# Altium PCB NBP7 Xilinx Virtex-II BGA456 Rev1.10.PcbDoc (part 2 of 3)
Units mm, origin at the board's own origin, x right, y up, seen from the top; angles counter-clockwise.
Board outline 69 x 80.99 mm, 6 copper layers (Top Layer, MidLayer1, InternalPlane1, InternalPlane2, MidLayer2, Bottom Layer); 101 components, 273 nets, 963 pads, 545 vias.
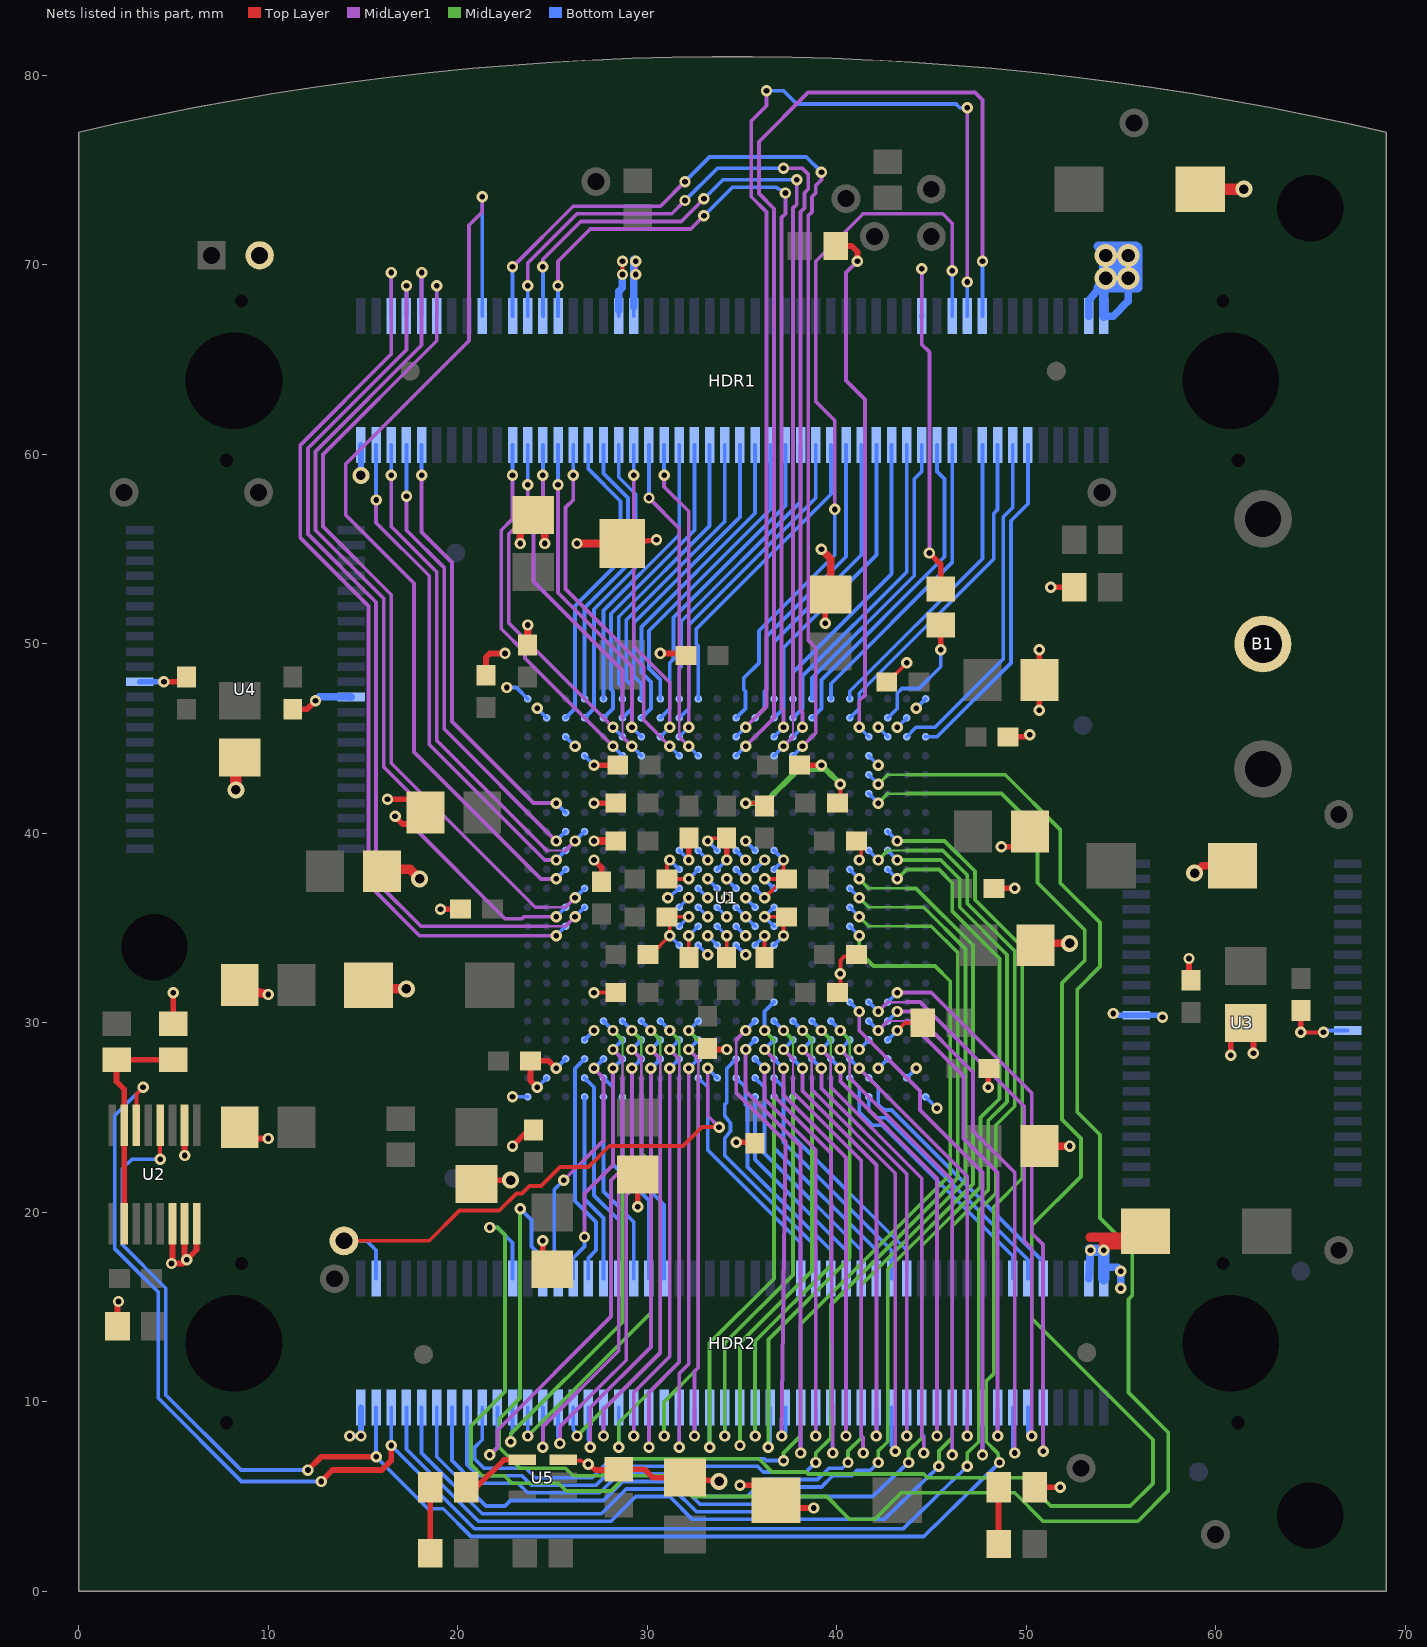
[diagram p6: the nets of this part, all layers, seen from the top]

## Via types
v1: diameter 0.6, hole 0.3, Top Layer to Bottom Layer, tented bottom, 520 vias
v2: diameter 0.9, hole 0.5, Top Layer to Bottom Layer, 17 vias
v3: diameter 1.2, hole 0.7, Top Layer to Bottom Layer, 8 vias

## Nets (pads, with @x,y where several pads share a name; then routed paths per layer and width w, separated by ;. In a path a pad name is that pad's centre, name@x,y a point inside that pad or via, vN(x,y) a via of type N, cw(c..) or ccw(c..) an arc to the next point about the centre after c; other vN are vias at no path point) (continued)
GND: B1.2 C1.2 C2.2 C3.2 C4.2 C5.2 C6.2 C7.2 C8.2 C9.2 C10.2 C11.2 C12.2 C13.2 C14.2 C15.2 C16.2 C17.2 C18.2 C19.2 C20.2 C22.2 C23.2 C24.2 C25.2 C26.2 C27.2 C28.2 C29.2 C30.2 C31.2 C32.2 C33.2 C34.2 C35.2 C36.2 C37.2 C38.2 C39.2 C40.2 C41.2 C42.2 C43.2 C44.2 C45.2 C46.2 C47.2 C48.2 C49.2 C50.2 C51.2 C52.2 C53.2 C54.2 C55.2 C56.2 C57.2 C58.2 C59.2 C60.2 C61.2 C62.2 HDR1.1 HDR1.36 HDR1.38 HDR1.98 HDR1.100 HDR2.1 HDR2.98 HDR2.100 JP1.2 LED1.2 R9.2 R10.1 U1.A1 U1.A22 U1.AA2 U1.AA21 U1.AB1 U1.AB22 U1.B2 U1.B21 U1.C3 U1.C20 U1.D4 U1.D19 U1.J9 U1.J10 U1.J11 U1.J12 U1.J13 U1.J14 U1.K9 U1.K10 U1.K11 U1.K12 U1.K13 U1.K14 U1.L9 U1.L10 U1.L11 U1.L12 U1.L13 U1.L14 U1.M9 U1.M10 U1.M11 U1.M12 U1.M13 U1.M14 U1.N9 U1.N10 U1.N11 U1.N12 U1.N13 U1.N14 U1.P9 U1.P10 U1.P11 U1.P12 U1.P13 U1.P14 U1.W4 U1.W19 U1.Y3 U1.Y20 U2.6 U2.7 U2.8 U2.10 U3.12 U3.34 U4.12 U4.34 U5.3 | length 241
  Top Layer w0.2: C7.2@8.5,44.3 8.638,44.092 8.9,43.7 C7.2@9,43.2 ; C3.2@20.5,22 20.639,21.414 C3.2@20.644,21.398 ; U5.3@25.6,7 25.9,6.9 26.5,6.9 v1(26.9,6.7) ; v1(27.2,31.6) C50.2@28.2,31.6 ; C45.2@28.2,39.6 C45.2@28.35,39.6 ; v1(28.7,69.5) v1(28.7,70.2) ; v1(29.5,20.3) C4.2@29.5,22 ; C43.2@30.05,33.6 30.2,33.6 v1(31.2,34.6) C32.2@31.2,35.6 ; C32.2@31.05,35.6 C32.2@31.2,35.6 ; v1(31.2,38.6) 31.05,38.45 C37.2@31.05,37.6 v1(32.2,37.6) ; C36.2@32.2,33.45 v1(32.2,34.6) ; v1(32.2,35.6) C32.2@31.2,35.6 ; v1(33.2,39.6) 33.3,39.6 33.45,39.75 C25.2@34.2,39.75 ; C26.2@34.2,33.45 v1(34.2,34.6) ; v1(35.2,41.6) C19.2@36.1,41.6 ; C20.2@36.2,33.45 v1(36.2,34.6) ; v1(36.2,35.6) C31.2@37.3,35.6 ; v1(36.2,36.6) 37,37.4 C30.2@37.1,37.4 ; v1(36.2,37.6) C30.2@37.35,37.6 37.35,37.75 37.2,37.9 v1(37.2,38.6) ; C56.2@36.8,4.4 v1(38.8,4.4) ; v1(37.2,34.6) C31.2@37.2,35.4 ; C48.2@40.05,31.6 40.2,31.6 v1(40.2,32.6) 40.2,33.3 40.4,33.5 40.7,33.5 40.994,33.412 C47.2@41.2,33.35 ; C44.2@40.2,41.6 v1(40.2,42.6) ; C46.2@40.95,39.35 C46.2@40.95,39.6 ; v1(41.2,38.6) 41.3,38.7 C46.2@41.3,39.4 ; C22.2@42.65,48 C22.2@42.7,48 ; C22.2@42.8,48 C22.2@42.7,48 ; v1(43.7,49) C22.2@42.7,48 ; C39.2@47.95,27.6 C39.2@48.05,27.6 C39.2@48.047,27.548 ; C34.2@48.6,45.1 C34.2@49.05,45.1 ; v1(49.4,37.1) v1@49.45,37.1 ; C16.2@49.5,40 C16.2@49.7,40.1 ; C13.2@50.4,47.7 50.7,47.76 C13.2@50.765,47.773 ; LED1.2@50.45,5.5 LED1.2@50.6,5.5 ; C15.2@50.825,23.975 51.325,24.35 50.7,24.2 50.94,23.72 50.98,23.64 51,23.6 51.1,23.4 51.1,23.5 51.1,23.7 C15.2@51.2,23.5 ; C33.2@58.5,32.35 C33.2@58.6,32.35 ; C33.2@58.6,32.3 C33.2@58.6,32.349 ; v1(58.6,33.4) C33.2@58.6,32.35 ; C33.2@58.7,32.25 C33.2@58.6,32.349 ; v1(60.8,28.3) C2.2@60.8,29.6 ; v1(62,28.4) C2.2@62,29.5 ; v1(64.5,29.5) v1(65.7,29.5) ; C33.2@58.6,32.349 58.5,32.35 C33.2@58.6,32.35
  Top Layer w0.3: R10.1@2.05,14 2.05,15.25 v1(2.1,15.3) ; v1(4.5,48) C41.2@5.7,48 ; C51.2@4.8,30.1 4.865,29.905 C51.2@5,29.5 ; U2.6@4.952,19.4 4.952,17.353 v1(4.9,17.3) 5.5,17.3 v1(5.7,17.5) ; C51.2@5,29.95 v1(5,31.6) ; U2.10@5.587,24.6 5.587,23.012 v1(5.6,23) ; U2.7@5.6,19.387 U2.7@5.587,19.4 5.587,17.612 v1(5.7,17.5) ; U2.8@6.222,19.4 6.222,18.023 v1(5.7,17.5) ; C9.2@8.5,23.9 v1(10,23.9) ; C42.2@11.3,46.55 12.05,46.55 v1(12.5,47) ; v1(16.3,41.8) 17.6,41.8 C11.2@17.9,41.7 ; v1(16.7,40.9) 17.1,40.5 C11.2@17.9,40.5 ; v1(19.1,36) C28.2@20.15,36 ; C3.2@21,21.7 v2(22.8,21.7) ; C24.2@21.5,48.3 C24.2@21.5,48.35 21.5,49.3 21.7,49.5 v1(22.5,49.5) ; v1(22.9,23.5) 23.75,24.35 C27.2@24,24.35 ; v1(24.2,26.6) 23.85,26.95 C38.2@23.85,28 24.8,28 v1(25.2,27.6) ; v1(24.5,18.5) 24.5,17.5 C14.2@24.9,17.5 ; v1(26.9,6.7) 27.3,6.4 C52.2@28.5,6.4 ; v1(27.2,38.6) 27.6,38.2 C59.2@27.6,37.45 ; v1(27.2,41.6) C49.2@28.3,41.6 ; v1(27.2,43.6) C61.2@28.45,43.6 ; C52.2@28.5,6.45 29.85,6.45 30.3,6 C1.2@32,6 v2(33.8,5.8) ; C53.2@28.7,55.3 v1(30.5,55.5) ; v1(29.5,20.3) C4.2@29.5,21.9 ; v1@30.7,49.6 v1(30.7,49.5) 31.8,49.5 C35.2@32.05,49.4 ; v1(32.2,38.6) C40.2@32.2,39.75 ; C62.2@33.2,28.65 33.25,28.6 v1(34.2,28.6) ; v1(34.2,38.6) C25.2@34.2,39.75 ; v1(34.7,23.7) C17.2@35.7,23.7 ; v1(34.9,5.6) C56.2@36.6,5.6 ; C56.2@36.5,4.4 36.8,4.4 v1(38.8,4.4) ; C60.2@38.05,43.6 38.35,43.75 38.3,43.6 v1(39.2,43.6) ; v1(39.4,51.1) 39.4,52.6 39.697,52.631 C5.2@39.7,52.631 ; C5.2@39.5,53 39.7,52.9 C5.2@39.7,52.644 ; C5.2@39.6,52.7 C5.2@39.7,52.644 ; C5.2@39.7,52.6 C5.2@39.7,52.631 ; v1(48,26.6) C39.2@48,27.55 ; C29.2@48.3,37.1 v1(49.4,37.1) ; v1(48.7,39.3) 49.4,39.3 C16.2@50.2,40.1 ; C34.2@49.05,45.1 49.9,45.1 ; LED1.2@50.6,5.5 v1(51.8,5.5) ; v1(50.7,46.5) 50.7,47.76 C13.2@50.7,48.1 v1(50.7,49.7) ; v1(51.3,53) R9.2@52.55,53 ; R9.2@52.55,52.9 R9.2@52.6,52.9 ; C33.2@58.6,32.35 v1(58.6,33.4) ; v1(60.8,28.3) C2.2@60.8,29.8 ; v1(62,28.4) C2.2@62,29.6 ; v1(64.5,29.5) C18.2@64.5,30.65 ; C5.2@39.7,52.631 39.719,52.633 C5.2@39.7,52.644 ; C5.2@39.7,52.631 C5.2@39.7,52.644
  Top Layer w0.4: C8.2@7.85,31.35 C8.2@7.9,31.4 ; v1(23.3,55.3) 23.3,56.3 C12.2@24,56.8 ; C23.2@23.7,50.1 v1(23.7,51) ; v1(24.6,55.3) C12.2@24.6,56.5 ; v1(26.3,55.3) C53.2@28.7,55.3 ; v1(27.2,39.6) C45.2@28.35,39.6 ; v1(39.2,55) 39.7,54.5 39.7,52.9 39.7,52.644 39.7,52.631 C5.2@39.7,52.6 ; C6.2@50.7,34.2 v2(52.3,34.2) ; C15.2@51.2,23.5 v1(52.3,23.5) ; v2(58.9,37.9) 59.3,38.3 C55.2@60.9,38.3
  Top Layer w0.5: C8.2@8.5,31.8 v1(10,31.5) ; C54.2@15.3,31.5 15.5,31.8 v2(17.3,31.8) ; C10.2@16,38.1 C10.2@16.9,38.1 ; C10.2@16.903,38.06 C10.2@16.9,38.1 ; v2(18,37.6) 17.5,38.1 C10.2@16.9,38.1 ; C6.2@50.5,34.2 C6.2@50.7,34.2 ; 53.4,18.7 54.1,18.7 ; v1(54.1,18) 54.1,18.3 ; C57.2@55.3,18.3 54.1,18.3 ; C57.2@56,18.7 54.1,18.7 ; 54.1,18.3 54.1,18.7
  Top Layer w0.6: v2(8.3,42.3) C7.2@8.3,44 ; C58.2@59.2,74 v2(61.5,74)
  MidLayer1 w0.2: v1(29.4,69.5) v1(29.4,70.2)
  MidLayer2 w0.3: v1(35.2,41.6) 36.2,41.6 38,43.4 39.2,43.4 39.4,43.4 v1(40.2,42.6)
  Bottom Layer w0.2: v1(22.6,47.7) 23.1,47.7 U1.AB1@23.7,47.1 ; v1(22.9,26.1) U1.A1@23.7,26.1 ; v1(24.2,26.6) U1.B2@24.7,27.1 ; v1(24.2,46.6) U1.AA2@24.7,46.1 ; v1(25.2,27.6) U1.C3@25.7,28.1 ; U1.Y3@25.7,45.1 v1(26.2,44.6) ; U1.D4@26.7,29.1 v1(27.2,29.6) ; U1.W4@26.7,44.1 v1(27.2,43.6) ; HDR1.36@28.5,67.3 HDR1.36@28.5,67.6 ; v1@29.2,69.3 29.3,69.4 v1(29.4,69.5) ; HDR1.38@29.3,67.3 HDR1.38@29.3,67.8 ; v1(31.1,36.6) U1.M9@31.7,37.1 ; v1(31.2,34.6) U1.J9@31.7,34.1 ; v1(31.2,38.6) U1.N9@31.7,38.1 ; U1.K9@31.7,35.1 v1(32.2,35.6) ; U1.L9@31.7,36.1 v1(32.2,36.6) ; U1.P9@31.7,39.1 v1(32.2,38.6) ; v1(32.2,34.6) U1.K10@32.7,35.1 ; v1(32.2,37.6) U1.N10@32.7,38.1 ; U1.J10@32.7,34.1 v1(33.2,33.6) ; U1.L10@32.7,36.1 v1(33.2,35.6) ; U1.M10@32.7,37.1 v1(33.2,36.6) ; U1.P10@32.7,39.1 v1(33.2,38.6) ; v1(33.2,34.6) U1.J11@33.7,34.1 ; v1(33.2,37.6) U1.M11@33.7,37.1 ; v1(33.2,39.6) U1.P11@33.7,39.1 ; U1.K11@33.7,35.1 v1(34.2,34.6) ; U1.N11@33.7,38.1 v1(34.2,38.6) ; U1.L11@33.7,36.1 v1(34.2,35.6) ; v1(34.2,37.6) U1.M12@34.7,37.1 ; U1.J12@34.7,34.1 v1(35.2,33.6) ; U1.K12@34.7,35.1 v1(35.2,34.6) ; U1.L12@34.7,36.1 v1(35.2,35.6) U1.K13@35.7,35.1 ; U1.N12@34.7,38.1 v1(35.2,37.6) ; U1.P12@34.7,39.1 v1(35.2,38.6) ; v1(35.2,36.6) U1.L13@35.7,36.1 ; v1(35.2,39.6) U1.P13@35.7,39.1 ; U1.J13@35.7,34.1 v1(36.2,34.6) ; U1.M13@35.7,37.1 v1(36.2,36.6) ; U1.N13@35.7,38.1 v1(36.2,38.6) ; v1(36.2,37.6) U1.M14@36.7,37.1 ; U1.J14@36.7,34.1 v1(37.2,34.6) ; U1.K14@36.7,35.1 v1(36.2,35.6) U1.L14@36.7,36.1 ; U1.N14@36.7,38.1 v1(37.2,38.6) U1.P14@36.7,39.1 ; v1(41.2,28.6) U1.D19@41.7,29.1 ; U1.W19@41.7,44.1 v1(42.2,43.6) ; v1(42.2,27.6) U1.C20@42.7,28.1 ; v1(42.2,45.6) U1.Y20@42.7,45.1 ; v1(43.2,45.6) U1.AA21@43.7,46.1 ; U1.B21@43.7,27.1 v1(44.2,27.6) ; v1(44.2,46.6) U1.AB22@44.7,47.1 ; U1.A22@44.7,26.1 v1(45.3,25.5) ; v1(54.6,30.5) U3.12@55.825,30.4 ; v1(65.7,29.5) 65.7,29.6 65.8,29.6 U3.34@66.975,29.6 ; U3.12@55.825,30.4 56.1,30.4 U3.12@55.825,30.4
  Bottom Layer w0.3: U4.12@3.225,48 v1(4.5,48) ; v1(14.3,8.2) v1(14.9,8.2) HDR2.1@14.9,9.7 ; v2(14.9,58.9) HDR1.1@14.9,60.5 ; v1(54.6,30.5) 54.7,30.4 U3.12@55.825,30.4 ; U3.12@55.825,30.4 56.1,30.4 57.2,30.4 v1(57.2,30.3) ; v1(65.7,29.5) v1@65.8,29.6
  Bottom Layer w0.4: v1(12.5,47) 12.71,47.21 U4.34@14.375,47.2 ; HDR1.36@28.5,67.6 28.5,68.6 28.7,68.8 v1(28.7,69.5) ; HDR1.38@29.3,67.8 29.3,69.4 29.3,69.5 29.3,70.2 v1@29.3,70.3 ; HDR2.98@53.3,16.5 v1(53.4,18) v1@53.3,18.1 ; HDR1.98@53.3,67.3 53.3,68.1 53.8,68.7 53.8,68.8 53.8,68.9 54.1,69.2 v3(54.2,69.3) v3(54.2,70.5) v3@54.2,70.6 ; HDR2.100@54.1,16.5 54.1,17.1 54.835,17.101 v1(55,16.9) v1(55,16) ; HDR1.100@54.1,67.3 54.6,67.3 55.4,68.1 55.4,68.8 v3(55.4,69.3) 55.4,69.5 v3(55.4,70.5)
  Bottom Layer w0.5: 53.8,68.8 v3@54.1,68.8 ; 53.8,71 54.2,71 55.4,71 55.8,71 55.85,70.95 55.9,70.9 55.9,70.5 55.9,69.3 55.9,68.8 55.8,68.8 ; HDR1.100@54.1,67.3 v3@54.1,68.8 ; v3@54.9,70.2 v3@54.9,69.3 ; v3@54.1,68.8 54.1,69.2 54.1,69.3 54.1,70.5 54.1,70.9 54.2,70.9 55.4,70.9 55.8,70.9 55.8,70.5 55.8,69.3 55.8,68.8 ; v3@54.1,68.8 54.2,68.8 55.4,68.8 v3@55.5,68.8 ; v3@54.9,69.3 v3@55.2,69.3 ; v3@54.9,69.3 54.5,69.3 54.6,69.4 54.6,70.5 54.6,70.6 54.7,70.5 54.8,70.5 55.1,70.2 55.2,70.1 v3@55.2,69.3 ; v3@55.2,69.3 55.3,69.4 55.4,69.5 55.5,69.6 55.5,69.3 v3@55.5,68.8 ; v3@55.5,68.8 55.8,68.8
  Bottom Layer w0.6: v1(53.4,18) v1(54.1,18) 54.1,17.1 HDR2.100@54.1,16.5
  other v1: 34.2,36.6 50.2,45.2
GREEN0: HDR1.10 U1.L3 | length 46.3
  MidLayer1 w0.2: v1(18.1,69.6) 18.1,65.763 12.5,60.163 12.5,56 16.1,52.4 16.1,43.5 17.533,42.067 17.533,40.467 22.5,35.5 23.4,35.5 23.5,35.6 v1(25.2,35.6)
  Bottom Layer w0.2: HDR1.10@18.1,67.3 v1(18.1,69.6) ; v1(25.2,35.6) U1.L3@25.7,36.1
GREEN1: HDR1.12 U1.M4 | length 44.5
  MidLayer1 w0.127: 24.7,36.1 25.7,36.1
  MidLayer1 w0.2: v1(18.9,68.9) 18.9,65.997 12.9,59.997 12.9,56.2 16.5,52.6 16.5,43.7 24.1,36.1 24.7,36.1 ; 25.7,36.1 v1(26.2,36.6)
  Bottom Layer w0.2: HDR1.12@18.9,67.3 v1(18.9,68.9) ; v1(26.2,36.6) U1.M4@26.7,37.1
HDRIVE: HDR1.18 U1.N3 | length 51.1
  MidLayer1 w0.2: v1(21.3,73.6) 21.3,72.8 20.6,72.1 20.6,66 14.1,59.5 14.1,56.8 17.7,53.2 17.7,44.3 24.4,37.6 v1(25.2,37.6)
  Bottom Layer w0.2: HDR1.18@21.3,67.3 v1(21.3,73.6) ; v1(25.2,37.6) U1.N3@25.7,38.1
IO0: HDR2.7 U1.P20 | length 72
  MidLayer2 w0.2: v1(43.2,38.6) 45.5,38.6 46.5,37.6 46.5,36.1 49,33.6 49,25.834 48,24.834 48,21.172 46.1,19.272 46.1,8.1 45.4,7.4 v1(45.4,6.6)
  Bottom Layer w0.2: HDR2.7@17.3,9.7 17.3,7.5 21.1,3.7 28.1,3.7 29.4,5 31.2,5 32.4,3.8 42.5,3.8 v1(45.4,6.6) ; U1.P20@42.7,39.1 v1(43.2,38.6)
IO1: HDR2.9 U1.N20 | length 69.2
  MidLayer2 w0.2: v1(43.2,37.6) 43.7,38.1 45.4,38.1 46.1,37.4 46.1,35.9 48.6,33.4 48.6,26 47.6,25 47.6,21.337 44.5,18.237 44.5,8.1 43.8,7.4 v1(43.8,6.8)
  Bottom Layer w0.2: HDR2.9@18.1,9.7 18.1,7.3 21.3,4.1 27.6,4.1 28.9,5.4 31.4,5.4 32.6,4.2 35.8,4.2 36.6,5 41.9,5 v1(43.8,6.8) ; U1.N20@42.7,38.1 v1(43.2,37.6)
IO2: HDR2.11 U1.N18 | length 66.4
  MidLayer2 w0.127: 41.7,37.1 43.7,37.1
  MidLayer2 w0.2: v1(41.2,37.6) 41.7,37.1 ; v1(42.2,6.8) 42.2,7.4 42.7,7.9 42.7,17.003 47.2,21.503 47.2,34.1 44.2,37.1 43.7,37.1
  Bottom Layer w0.2: HDR2.11@18.9,9.7 18.9,7.1 21.5,4.5 22.5,4.5 22.8,4.8 27.7,4.8 28.7,5.8 31.6,5.8 32.8,4.6 35.5,4.6 36.4,5.5 39.2,5.5 39.8,6.1 40.8,6.1 41.085,6.385 41.8,6.4 v1(42.2,6.8) ; U1.N18@40.7,38.1 v1(41.2,37.6)
IO3: HDR2.13 U1.M18 | length 63.2
  MidLayer2 w0.127: 41.7,36.1 43.7,36.1
  MidLayer2 w0.2: v1(40.6,6.8) 40.6,7.4 41.3,8.1 41.3,16.169 46.8,21.669 46.8,33.9 44.6,36.1 43.7,36.1 ; v1(41.2,36.6) 41.7,36.1
  Bottom Layer w0.2: HDR2.13@19.7,9.7 19.7,6.9 20.9,5.7 23.2,5.7 23.7,5.2 27.5,5.2 28.5,6.2 31.8,6.2 33,5 35.3,5 36.2,5.9 39,5.9 39.6,6.5 40.3,6.5 v1(40.6,6.8) ; U1.M18@40.7,37.1 v1(41.2,36.6)
IO4: HDR2.15 U1.L18 | length 59.3
  MidLayer2 w0.127: 41.7,35.1 43.7,35.1
  MidLayer2 w0.2: v1(38.9,6.8) 38.9,7.3 39.7,8.1 39.7,15.134 46.4,21.834 46.4,33.7 45,35.1 43.7,35.1 ; v1(41.2,35.6) 41.7,35.1
  Bottom Layer w0.2: HDR2.15@20.5,9.7 20.5,6.7 21.1,6.1 23.4,6.1 23.9,5.6 27.3,5.6 28.3,6.6 35.834,6.6 36.134,6.3 38.4,6.3 38.5,6.4 v1(38.9,6.8) ; U1.L18@40.7,36.1 v1(41.2,35.6)
IO5: HDR2.17 U1.K18 | length 56
  MidLayer2 w0.2: v1(37.2,6.9) 37.2,7.3 38.1,8.2 38.1,14.1 46,22 46,32.2 45.2,33 41.949,33 41.2,33.749 v1(41.2,34.6)
  Bottom Layer w0.2: HDR2.17@21.3,9.7 21.3,8 20.9,7.6 20.9,7 21.4,6.5 23.6,6.5 24.1,6 27.1,6 28.1,7 36.2,7 36.3,6.9 v1(37.2,6.9) ; U1.K18@40.7,35.1 v1(41.2,34.6)
IO6: HDR2.19 U1.D6 | length 27.9
  MidLayer1 w0.127: 28.7,27.1 28.7,28.1
  MidLayer1 w0.2: v1(21.7,7.2) 22.1,7.6 22.1,8.5 28.1,14.5 28.1,21.7 28.7,22.3 28.7,27.1 ; v1(28.2,28.6) 28.7,28.1
  Bottom Layer w0.2: v1(21.7,7.2) 22.1,7.6 HDR2.19@22.1,9.7 ; v1(28.2,28.6) U1.D6@28.7,29.1
IO7: HDR2.21 U1.E5 | length 26.9
  MidLayer2 w0.127: 28.7,27.1 28.7,29.1
  MidLayer2 w0.2: v1(22.8,7.9) 22.8,8.3 28.7,14.2 28.7,27.1 ; v1(28.2,29.6) 28.7,29.1
  Bottom Layer w0.2: v1(22.8,7.9) 22.8,8.3 22.9,8.4 HDR2.21@22.9,9.7 ; U1.E5@27.7,30.1 v1(28.2,29.6)
IO8: HDR2.23 U1.E6 | length 26.7
  MidLayer2 w0.127: 29.7,27.1 29.7,29.1
  MidLayer2 w0.2: v1(23.7,8.2) 30.2,14.7 30.2,22.6 29.7,23.1 29.7,27.1 ; v1(29.2,29.6) 29.7,29.1
  Bottom Layer w0.2: v1(23.7,8.2) HDR2.23@23.7,9.7 ; U1.E6@28.7,30.1 v1(29.2,29.6)
IO9: HDR2.25 U1.C7 | length 24.8
  MidLayer1 w0.2: v1(24.5,7.6) 24.5,8.7 28.5,12.7 28.5,21.3 29.2,22 v1(29.2,27.6)
  Bottom Layer w0.2: v1(24.5,7.6) 24.5,8.2 HDR2.25@24.5,9.7 ; v1(29.2,27.6) U1.C7@29.7,28.1
IO10: HDR2.27 U1.D7 | length 25.5
  MidLayer1 w0.127: 29.7,27.1 29.7,28.1
  MidLayer1 w0.2: v1(25.4,7.8) 25.4,8.7 27.664,10.964 28.9,12.2 28.9,20.9 29.7,21.7 29.7,27.1 ; v1(29.2,28.6) 29.7,28.1
  Bottom Layer w0.2: v1@25.3,7.7 v1(25.4,7.8) 25.3,8.2 HDR2.27@25.3,9.7 ; v1(29.2,28.6) U1.D7@29.7,29.1
IO11: HDR2.29 U1.E7 | length 25.9
  MidLayer2 w0.127: 30.7,27.1 30.7,29.1
  MidLayer2 w0.2: v1(26.3,8.2) 30.7,12.6 30.7,27.1 ; v1(30.2,29.6) 30.7,29.1
  Bottom Layer w0.2: v1@26.1,8.2 v1(26.3,8.2) 26.1,8.6 HDR2.29@26.1,9.7 ; U1.E7@29.7,30.1 v1(30.2,29.6)
IO12: HDR2.31 U1.C8 | length 24.2
  MidLayer1 w0.2: v1(27,7.6) 27,9.7 30.2,12.9 v1(30.2,27.6)
  Bottom Layer w0.2: v1@26.9,7.6 v1(27,7.6) 26.9,8.1 HDR2.31@26.9,9.7 ; v1(30.2,27.6) U1.C8@30.7,28.1
IO13: HDR2.33 U1.D8 | length 24.1
  MidLayer1 w0.127: 30.7,27.1 30.7,28.1
  MidLayer1 w0.2: v1(27.7,8.2) 27.7,9.6 30.7,12.6 30.7,27.1 ; v1(30.2,28.6) 30.7,28.1
  Bottom Layer w0.2: v1(27.7,8.2) HDR2.33@27.7,9.7 ; v1(30.2,28.6) U1.D8@30.7,29.1
IO14: HDR2.35 U1.E8 | length 26.3
  MidLayer2 w0.127: 31.7,27.1 31.7,29.1
  MidLayer2 w0.2: v1(28.5,7.6) 28.5,8.9 31.7,12.1 31.7,27.1 ; v1(31.2,29.6) 31.7,29.1
  Bottom Layer w0.2: v1(28.5,7.6) HDR2.35@28.5,9.7 ; U1.E8@30.7,30.1 v1(31.2,29.6)
IO15: HDR2.37 U1.C9 | length 22.4
  MidLayer1 w0.2: v1(29.3,8.2) 29.3,10.5 31.2,12.4 v1(31.2,27.6)
  Bottom Layer w0.2: v1(29.3,8.2) HDR2.37@29.3,9.7 ; v1(31.2,27.6) U1.C9@31.7,28.1
IO16: HDR2.39 U1.D9 | length 24.7
  MidLayer1 w0.127: 31.7,27.1 31.7,28.1
  MidLayer1 w0.2: v1(30.1,7.6) 30.1,10.5 31.7,12.1 31.7,27.1 ; v1(31.2,28.6) 31.7,28.1
  Bottom Layer w0.2: v1(30.1,7.6) HDR2.39@30.1,9.7 ; v1(31.2,28.6) U1.D9@31.7,29.1
IO17: HDR2.41 U1.E10 | length 24.6
  MidLayer2 w0.127: 32.7,27.1 32.7,28.1
  MidLayer2 w0.2: v1(30.9,8.2) 30.9,10 32.7,11.8 32.7,27.1 ; v1(32.2,29.6) 32.8,29 32.8,28.2 32.7,28.1
  Bottom Layer w0.2: v1(30.9,8.2) HDR2.41@30.9,9.7 ; v1(32.2,29.6) U1.E10@32.7,30.1
IO18: HDR2.43 U1.C10 | length 23
  MidLayer1 w0.2: v1(31.7,7.6) 31.7,11.5 32.2,12 v1(32.2,27.6)
  Bottom Layer w0.2: v1(31.7,7.6) HDR2.43@31.7,9.7 ; v1(32.2,27.6) U1.C10@32.7,28.1
IO19: HDR2.45 U1.D10 | length 22.9
  MidLayer1 w0.127: 32.7,27.1 32.7,28.1
  MidLayer1 w0.2: v1(32.2,28.6) 32.7,28.1 ; v1(32.5,8.2) 32.5,11.6 32.7,11.8 32.7,27.1
  Bottom Layer w0.2: v1(32.2,28.6) U1.D10@32.7,29.1 ; v1(32.5,8.2) HDR2.45@32.5,9.7
IO20: HDR2.47 U1.F14 | length 27.4
  MidLayer2 w0.127: 36.7,27.1 36.7,29.1
  MidLayer2 w0.2: v1(33.3,7.6) 33.3,13.1 36.7,16.5 36.7,27.1 ; v1(36.2,29.6) 36.7,29.1
  Bottom Layer w0.2: v1(33.3,7.6) HDR2.47@33.3,9.7 ; v1(36.2,29.6) 36.2,30.6 U1.F14@36.7,31.1
IO21: HDR2.49 U1.E14 | length 25.3
  MidLayer2 w0.127: 37.7,27.1 37.7,29.1
  MidLayer2 w0.2: v1(34.1,8.2) 34.1,13.1 37.7,16.7 37.7,27.1 ; v1(37.2,29.6) 37.7,29.1
  Bottom Layer w0.2: v1(34.1,8.2) HDR2.49@34.1,9.7 ; U1.E14@36.7,30.1 v1(37.2,29.6)
IO22: HDR2.51 U1.E15 | length 26.4
  MidLayer2 w0.127: 38.7,27.1 38.7,29.1
  MidLayer2 w0.2: v1(34.9,7.7) 34.9,13.1 38.7,16.9 38.7,27.1 ; v1(38.2,29.6) 38.7,29.1
  Bottom Layer w0.2: v1(34.9,7.7) HDR2.51@34.9,9.7 ; U1.E15@37.7,30.1 v1(38.2,29.6)
IO23: HDR2.53 U1.E16 | length 25.5
  MidLayer2 w0.127: 39.7,27.1 39.7,29.1
  MidLayer2 w0.2: v1(35.7,8.2) 35.7,13.2 39.7,17.2 39.7,27.1 ; v1(39.2,29.6) 39.7,29.1
  Bottom Layer w0.2: v1(35.7,8.2) HDR2.53@35.7,9.7 ; U1.E16@38.7,30.1 v1(39.2,29.6)
IO24: HDR2.55 U1.E17 | length 26.8
  MidLayer2 w0.127: 40.7,27.1 40.7,29.1
  MidLayer2 w0.2: v1(36.4,7.6) 36.4,13.3 40.7,17.6 40.7,27.1 ; v1(40.2,29.6) 40.7,29.1
  Bottom Layer w0.2: v1@36.5,7.6 HDR2.55@36.5,9.7 ; U1.E17@39.7,30.1 v1(40.2,29.6)
IO25: HDR2.57 U1.E13 | length 25
  MidLayer1 w0.127: 34.7,28.1 34.7,29.1
  MidLayer1 w0.2: 34.7,28.1 34.7,26.334 37.3,23.734 v1(37.1,8.2) ; 34.7,29.1 v1(35.2,29.6)
  Bottom Layer w0.2: v1(35.2,29.6) U1.E13@35.7,30.1 ; v1(37.1,8.2) 37.3,8.4 HDR2.57@37.3,9.7
IO26: HDR2.59 U1.D13 | length 25.6
  MidLayer1 w0.2: v1(35.2,28.6) 35.2,26.4 38.1,23.5 v1(38.1,7.3)
  Bottom Layer w0.2: v1(35.2,28.6) U1.D13@35.7,29.1 ; v1(38.1,7.3) HDR2.59@38.1,9.7
IO27: HDR2.61 U1.C13 | length 22.7
  MidLayer1 w0.2: v1(36.2,27.6) 36.2,26 38.9,23.3 v1(38.9,8.2)
  Bottom Layer w0.2: U1.C13@35.7,28.1 v1(36.2,27.6) ; v1(38.9,8.2) HDR2.61@38.9,9.7
IO28: HDR2.63 U1.D14 | length 25.9
  MidLayer1 w0.127: 36.7,27.1 36.7,28.1
  MidLayer1 w0.2: v1(36.2,28.6) 36.7,28.1 ; 36.7,27.1 36.7,26.134 39.7,23.134 v1(39.8,7.3)
  Bottom Layer w0.2: v1(36.2,28.6) U1.D14@36.7,29.1 ; HDR2.63@39.7,9.7 v1(39.8,7.3)
IO29: HDR2.65 U1.C14 | length 23
  MidLayer1 w0.2: v1(37.2,27.6) 37.2,26.2 40.5,22.9 v1(40.5,8.2)
  Bottom Layer w0.2: U1.C14@36.7,28.1 v1(37.2,27.6) ; v1(40.5,8.2) HDR2.65@40.5,9.7
IO30: HDR2.67 U1.D15 | length 26.2
  MidLayer1 w0.127: 37.7,27.1 37.7,28.1
  MidLayer1 w0.2: v1(37.2,28.6) 37.7,28.1 ; 37.7,27.1 37.7,26.337 41.3,22.737 41.3,8.2 41.4,8.1 v1(41.4,7.3)
  Bottom Layer w0.2: v1(37.2,28.6) U1.D15@37.7,29.1 ; HDR2.67@41.3,9.7 41.3,8.2 41.4,8.1 v1(41.4,7.3)
IO31: HDR2.69 U1.C15 | length 23.2
  MidLayer1 w0.2: v1(38.2,27.6) 38.2,26.403 42.1,22.503 v1(42.1,8.2)
  Bottom Layer w0.2: U1.C15@37.7,28.1 v1(38.2,27.6) ; v1(42.1,8.2) HDR2.69@42.1,9.7
IO32: HDR2.71 U1.D16 | length 26.3
  MidLayer1 w0.127: 38.7,27.1 38.7,28.1
  MidLayer1 w0.2: v1(38.2,28.6) 38.7,28.1 ; 38.7,27.1 38.7,26.469 43.1,22.069 v1(43.1,7.4)
  Bottom Layer w0.2: v1(38.2,28.6) U1.D16@38.7,29.1 ; HDR2.71@42.9,9.7 42.9,7.7 v1(43.1,7.4)
IO33: HDR2.73 U1.C16 | length 23.5
  MidLayer1 w0.2: v1(39.2,27.6) 39.2,26.534 43.7,22.034 v1(43.7,8.2)
  Bottom Layer w0.2: U1.C16@38.7,28.1 v1(39.2,27.6) ; v1(43.7,8.2) HDR2.73@43.7,9.7
IO34: HDR2.75 U1.D17 | length 26.8
  MidLayer1 w0.127: 39.7,27.1 39.7,28.1
  MidLayer1 w0.2: v1(39.2,28.6) 39.7,28.1 ; 39.7,27.1 39.7,26.6 44.5,21.8 44.5,8.2 44.6,8.1 v1(44.6,7.3)
  Bottom Layer w0.2: v1(39.2,28.6) U1.D17@39.7,29.1 ; v1@44.5,7.3 v1(44.6,7.3) 44.6,8.2 44.5,8.3 HDR2.75@44.5,9.7
IO35: HDR2.77 U1.C17 | length 23.7
  MidLayer1 w0.2: v1(40.2,27.6) 40.2,26.9 45.3,21.8 v1(45.3,8.2)
  Bottom Layer w0.2: U1.C17@39.7,28.1 v1(40.2,27.6) ; v1(45.3,8.2) HDR2.77@45.3,9.7
JIOA0: HDR1.3 U1.P3 | length 26.7
  MidLayer1 w0.2: v1(15.7,57.6) 15.7,56.4 18.5,53.6 18.5,44.7 24.6,38.6 v1(25.2,38.6)
  Bottom Layer w0.2: v1@15.7,57.8 HDR1.3@15.7,60.5 ; v1(25.2,38.6) U1.P3@25.7,39.1
JIOA1: HDR1.5 U1.R4 | length 27.2
  MidLayer1 w0.127: 24.7,39.1 25.7,39.1
  MidLayer1 w0.2: v1(16.5,58.9) 16.5,56.2 18.9,53.8 18.9,44.9 24.7,39.1 ; 25.7,39.1 v1(26.2,39.6)
  Bottom Layer w0.2: v1(16.5,58.9) HDR1.5@16.5,60.5 ; v1(26.2,39.6) U1.R4@26.7,40.1
JIOA2: HDR1.7 U1.R3 | length 24.9
  MidLayer1 w0.2: v1(17.3,57.8) 17.3,56 19.3,54 19.3,45.5 v1(25.2,39.6)
  Bottom Layer w0.2: v1(17.3,57.8) HDR1.7@17.3,60.5 ; v1(25.2,39.6) U1.R3@25.7,40.1
JIOA3: HDR1.9 U1.T3 | length 23.3
  MidLayer1 w0.2: v1(18.1,58.9) 18.1,55.9 19.7,54.3 19.7,45.9 24,41.6 v1(25.2,41.6)
  Bottom Layer w0.2: v1(18.1,58.9) HDR1.9@18.1,60.5 ; v1(25.2,41.6) U1.T3@25.7,41.1
JIOB0: HDR1.83 U1.AB18 | length 16.3
  Bottom Layer w0.2: U1.AB18@40.7,47.1 40.7,47.5 47.7,54.5 HDR1.83@47.7,60.5
JIOB1: HDR1.85 U1.AA18 | length 17.6
  Bottom Layer w0.2: U1.AA18@40.7,46.1 41.2,46.6 41.2,47.4 48.3,54.5 48.3,56.9 48.5,57.1 HDR1.85@48.5,60.5
JIOB2: HDR1.87 U1.Y21 | length 18.3
  Bottom Layer w0.2: U1.Y21@43.7,45.1 44.2,45.6 45.2,45.6 48.8,49.2 48.8,56.7 49.3,57.2 HDR1.87@49.3,60.5
JIOB3: HDR1.89 U1.Y22 | length 18
  Bottom Layer w0.2: U1.Y22@44.7,45.1 45.3,45.1 49.2,49 49.2,56.5 50.1,57.4 HDR1.89@50.1,60.5
KBCLOCK: HDR1.22 U1.W15 | length 53.4
  MidLayer1 w0.2: v1(22.9,69.9) 26.1,73.1 30.7,73.1 v1(32,74.4) ; v1(38.2,44.6) 38.9,45.3 38.9,49.8 38.5,50.2 38.5,72.6 38.7,72.8 38.7,73.6 38.9,73.8 38.9,74.2 39.2,74.5 v1(39.2,74.9)
  Bottom Layer w0.2: HDR1.22@22.9,67.3 v1(22.9,69.9) ; v1(32,74.4) 33.3,75.7 38.4,75.7 v1(39.2,74.9) ; U1.W15@37.7,44.1 v1(38.2,44.6)
KBDATA: HDR1.24 U1.Y15 | length 49.9
  MidLayer1 w0.2: v1(23.7,68.9) 23.7,70.1 26.3,72.7 31.3,72.7 v1(32,73.4) ; v1(37.2,75.1) 38.2,75.1 38.5,74.8 38.5,74 38.3,73.8 38.3,73 38.1,72.8 38.1,46.5 38.2,46.4 v1(38.2,45.6)
  Bottom Layer w0.2: HDR1.24@23.7,67.3 v1(23.7,68.9) ; v1(32,73.4) 33.7,75.1 v1(37.2,75.1) ; U1.Y15@37.7,45.1 v1(38.2,45.6)
LCD_BCKL: HDR2.22 U1.V19 | length 107.9
  MidLayer2 w0.127: 42.7,43.1 43.7,43.1
  MidLayer2 w0.2: v1(21.7,19.2) 22.1,19.2 22.5,18.8 22.5,10.531 20.7,8.731 20.7,6.7 21.3,6.1 22.469,6.1 22.869,5.7 25.334,5.7 25.734,5.3 28.1,5.3 28.9,6.1 31.3,6.1 32.4,5 39.5,5 40.4,4.1 40.7,3.8 42,3.8 43.4,5.2 49.4,5.2 50.9,3.7 55.9,3.7 57.5,5.3 57.5,8.4 55.4,10.5 55.4,15.4 55.6,15.6 55.6,18 53.9,19.7 53.9,24.1 53.017,24.983 52.7,25.3 52.7,31.769 53.9,32.969 53.9,35.3 51.8,37.4 51.8,40.2 48.9,43.1 43.7,43.1 ; v1(42.2,42.6) 42.7,43.1
  Bottom Layer w0.2: v1(21.7,19.2) 22.1,19.2 22.9,18.4 HDR2.22@22.9,16.5 ; U1.V19@41.7,43.1 v1(42.2,42.6)
LCD_E: HDR2.26 U1.U19 | length 104.7
  MidLayer2 w0.127: 42.7,42.1 43.7,42.1
  MidLayer2 w0.2: 23.2,6.5 23.3,6.5 ; v1(23.3,20.2) 23.3,10.2 22.2,9.1 22.2,7.6 23.3,6.5 ; v1(42.2,41.6) 42.7,42.1 ; 43.7,42.1 48.7,42.1 50.6,40.2 50.6,37.4 53.1,34.9 53.1,33.3 51.9,32.1 51.9,24.9 52.9,23.9 52.9,21.9 50.3,19.3 50.3,14.4 56.7,8 56.7,5.7 55.5,4.5 51.3,4.5 49.8,6 44.8,6 44.6,6.2 38.5,6.2 38.4,6.3 36.6,6.3 35.9,7 28.5,7 27.6,6.1 26.1,6.1 25.7,6.5 23.3,6.5
  Bottom Layer w0.2: v1(23.3,20.2) 23.9,19.6 23.9,18.2 24.5,17.6 HDR2.26@24.5,16.5 ; U1.U19@41.7,42.1 v1(42.2,41.6)
LED0: HDR2.60 U1.B10 | length 12.8
  Bottom Layer w0.2: U1.B10@32.7,27.1 33.2,26.6 33.2,23.3 38.1,18.4 HDR2.60@38.1,16.5
LED1: HDR2.62 U1.C12 | length 14
  Bottom Layer w0.2: U1.C12@34.7,28.1 34.2,27.6 34.2,25.8 34.1,25.7 34.1,25.1 34.4,24.7 34.4,24.3 34.1,23.9 34.1,23 38.9,18.2 38.9,18 HDR2.62@38.9,16.5
LED2: HDR2.64 U1.B12 | length 12.7
  Bottom Layer w0.2: U1.B12@34.7,27.1 35.2,26.6 35.2,25.7 35.3,25.6 35.3,22.4 39.7,18 HDR2.64@39.7,16.5
LED3: HDR2.66 U1.A13 | length 11.6
  Bottom Layer w0.2: U1.A13@35.7,26.1 35.7,22.8 40.5,18 HDR2.66@40.5,16.5
LED4: HDR2.68 U1.B13 | length 12.9
  Bottom Layer w0.2: U1.B13@35.7,27.1 36.2,26.6 36.2,23.1 41.3,18 HDR2.68@41.3,16.5
LED5: HDR2.70 U1.A14 | length 11.8
  Bottom Layer w0.2: U1.A14@36.7,26.1 36.7,23.4 42.1,18 HDR2.70@42.1,16.5
LED6: HDR2.72 U1.B14 | length 13.2
  Bottom Layer w0.2: U1.B14@36.7,27.1 37.2,26.6 37.2,23.7 42.9,18 HDR2.72@42.9,16.5
LED7: HDR2.74 U1.A15 | length 12.1
  Bottom Layer w0.2: U1.A15@37.7,26.1 37.7,24 43.7,18 HDR2.74@43.7,16.5
MOUSECLOCK: HDR1.26 U1.W14 | length 49
  MidLayer1 w0.127: 37.7,45.1 37.7,46.1
  MidLayer1 w0.2: v1(24.5,69.9) 24.5,70.3 26.5,72.3 31.8,72.3 v1(33,73.5) ; v1(37.2,44.6) 37.7,45.1 ; 37.7,46.1 37.7,73 37.9,73.2 v1(37.9,74.5)
  Bottom Layer w0.2: HDR1.26@24.5,67.3 v1(24.5,69.9) ; v1(33,73.5) 34,74.5 v1(37.9,74.5) ; U1.W14@36.7,44.1 v1(37.2,44.6)
MOUSEDATA: HDR1.28 U1.Y14 | length 45.6
  MidLayer1 w0.2: v1(25.3,68.9) 25.3,70.2 27,71.9 32.3,71.9 v1(33,72.6) ; v1(37.2,45.6) 37.2,46.5 37.1,46.6 37.1,72.5 37.3,72.7 v1(37.3,73.8)
  Bottom Layer w0.2: HDR1.28@25.3,67.3 v1(25.3,68.9) ; v1(33,72.6) 34.5,74.1 36.8,74.1 v1(37.3,73.8) ; U1.Y14@36.7,45.1 v1(37.2,45.6)
NetC51_1: C51.1 R4.2 U2.2 U2.15 | length 11.8
  Top Layer w0.3: U2.2@2.412,19.4 U2.15@2.412,24.6 2.412,26.488 2,26.9 R4.2@2,28.05 C51.1@5,28.05
NetHDR1_76: HDR1.76 R1.2 | length 19.8
  Top Layer w0.3: v1(44.9,54.8) 45.5,54.2 R1.2@45.5,52.9
  MidLayer1 w0.2: v1(44.5,69.8) 44.5,65.8 44.9,65.4 v1(44.9,54.8)
  Bottom Layer w0.2: HDR1.76@44.5,67.3 v1(44.5,69.8)
NetLED1_1: LED1.1 R11.1 | length 3
  Top Layer w0.3: R11.1@48.55,2.5 LED1.1@48.55,5.5
NetLED2_1: LED2.1 R12.1 | length 3.5
  Top Layer w0.3: R12.1@18.55,2 LED2.1@18.55,5.5
NetLED2_2: LED2.2 U5.4 | length 3.6
  Top Layer w0.3: LED2.2@20.45,5.5 21,5.5 22.441,6.941 U5.4@23.42,6.941
NetR2_2: R2.2 U1.Y19 | length 27.9
  Top Layer w0.3: R2.2@39.95,71 40.8,71 41.1,70.7 v1(41.1,70.2)
  MidLayer1 w0.2: v1(41.1,70.2) 40.5,69.6 40.5,63.9 41.5,62.9 41.5,47.3 41.2,47 v1(41.2,45.6)
  Bottom Layer w0.2: v1(41.2,45.6) U1.Y19@41.7,45.1
NetR3_2: R3.2 U1.D20 | length 2.2
  Top Layer w0.2: v1(43.2,29.6) 43.6,30 R3.2@44.55,30
  Bottom Layer w0.2: U1.D20@42.7,29.1 v1(43.2,29.6)
NEXUS_TCK: HDR1.82 U1.Y12 | length 57.4
  MidLayer1 w0.2: v1(35.2,45.6) 36.3,46.7 36.3,72.8 35.5,73.6 35.5,77.6 36.3,78.4 v1(36.3,79.2) ; v1(46.9,69.1) v1(46.9,78.3)
  Bottom Layer w0.2: U1.Y12@34.7,45.1 v1(35.2,45.6) ; v1(36.3,79.2) 37.2,79.2 37.9,78.5 46.3,78.5 46.5,78.3 v1(46.9,78.3) ; HDR1.82@46.9,67.3 v1(46.9,69.1)
NEXUS_TDI: HDR1.84 U1.W12 | length 58
  MidLayer1 w0.2: v1(35.2,44.6) 36.7,46.1 36.7,72.966 35.9,73.766 35.9,76.5 38.5,79.1 47.3,79.1 47.7,78.7 v1(47.7,70.2)
  Bottom Layer w0.2: U1.W12@34.7,44.1 v1(35.2,44.6) ; HDR1.84@47.7,67.3 v1(47.7,70.2)
NEXUS_TDO: R1.1 U1.AA20 | length 6.6
  Top Layer w0.3: v1(45.5,49.7) R1.1@45.5,51
  Bottom Layer w0.2: U1.AA20@42.7,46.1 43.2,46.6 43.2,47.4 43.447,47.647 44.347,47.647 45.5,48.8 v1(45.5,49.7)
NEXUS_TMS: HDR1.80 U1.AA12 | length 40.1
  MidLayer1 w0.2: v1(39.9,57.1) 39.9,61.8 38.9,62.8 38.9,70.2 41.3,72.6 41.4,72.7 45.6,72.7 46.1,72.2 v1(46.1,69.7)
  Bottom Layer w0.2: U1.AA12@34.7,46.1 35.2,46.6 35.2,47.5 35.1,47.6 35.1,48.2 35.9,49 35.9,50.7 39.9,54.7 v1(39.9,57.1) ; HDR1.80@46.1,67.3 46.1,68.9 v1(46.1,69.7)
RAM0_DATA0: HDR2.42 U1.A6 | length 10.5
  Bottom Layer w0.2: U1.A6@28.7,26.1 28.7,22.6 30.9,20.4 HDR2.42@30.9,16.5
RAM0_DATA1: HDR2.40 U1.B5 | length 11.6
  Bottom Layer w0.2: U1.B5@27.7,27.1 28.2,26.6 28.2,22.534 30.1,20.634 HDR2.40@30.1,16.5
RAM0_DATA2: HDR2.38 U1.A5 | length 10.3
  Bottom Layer w0.2: U1.A5@27.7,26.1 27.7,21.1 29.3,19.5 HDR2.38@29.3,16.5
RAM0_DATA3: HDR2.36 U1.B4 | length 11.3
  Bottom Layer w0.2: U1.B4@26.7,27.1 27.2,26.6 27.2,20.9 28.5,19.6 HDR2.36@28.5,16.5
RAM0_DATA4: HDR2.34 U1.A4 | length 10
  Bottom Layer w0.2: U1.A4@26.7,26.1 26.7,20.7 27.7,19.7 HDR2.34@27.7,16.5
RAM0_DATA5: HDR2.32 U1.C4 | length 12.4
  Bottom Layer w0.2: U1.C4@26.7,28.1 26.2,27.6 26.2,20.6 27.3,19.5 27.3,18 26.9,17.6 HDR2.32@26.9,16.5
RAM0_DATA6: HDR2.30 U1.C6 | length 12.7
  MidLayer1 w0.2: v1(26.7,18.7) 26.7,21 28.2,22.5 v1(28.2,27.6)
  Bottom Layer w0.2: HDR2.30@26.1,16.5 26.1,17.6 26.7,18.2 v1(26.7,18.7) ; v1(28.2,27.6) U1.C6@28.7,28.1
RAM0_DATA7: HDR2.28 U1.C5 | length 13.2
  MidLayer1 w0.2: v1(25.6,21.7) 27.7,23.8 27.7,27.1 v1(27.2,27.6)
  Bottom Layer w0.2: HDR2.28@25.3,16.5 25.3,17.8 25.1,18 25.1,21.2 v1(25.6,21.7) ; v1(27.2,27.6) U1.C5@27.7,28.1
RAM0_OE: HDR1.41 U1.Y9 | length 16.1
  MidLayer1 w0.2: v1(30.9,58.9) 30.9,58.3 32.2,57 v1(32.2,45.6)
  Bottom Layer w0.2: v1(30.9,58.9) 30.9,59.1 HDR1.41@30.9,60.5 ; U1.Y9@31.7,45.1 v1(32.2,45.6)
RAM0_WE: HDR1.79 U1.AB17 | length 16.1
  Bottom Layer w0.2: U1.AB17@39.7,47.1 39.7,47.9 46.1,54.3 HDR1.79@46.1,60.5
RAM1_DATA0: HDR1.45 U1.AA5 | length 16.5
  Bottom Layer w0.2: U1.AA5@27.7,46.1 28.2,46.6 28.2,47.5 28.1,47.6 28.1,51.597 32.5,55.997 HDR1.45@32.5,60.5
RAM1_DATA1: HDR1.49 U1.AA6 | length 16.9
  Bottom Layer w0.2: U1.AA6@28.7,46.1 29.2,46.6 29.2,47.8 28.9,48.1 28.9,51.266 34.1,56.466 HDR1.49@34.1,60.5
RAM1_DATA2: HDR1.53 U1.AA7 | length 17.3
  Bottom Layer w0.2: U1.AA7@29.7,46.1 30.2,46.6 30.2,48 29.7,48.5 29.7,50.9 35.7,56.9 HDR1.53@35.7,60.5
RAM1_DATA3: HDR1.57 U1.AA8 | length 17.1
  Bottom Layer w0.2: U1.AA8@30.7,46.1 31.2,46.6 31.2,49 31.4,49.2 31.4,51.4 37.3,57.3 HDR1.57@37.3,60.5
RAM1_DATA4: HDR1.55 U1.AB8 | length 16.3
  Bottom Layer w0.2: U1.AB8@30.7,47.1 30.7,48.1 30.1,48.7 30.1,50.7 31.3,51.9 36.5,57.1 HDR1.55@36.5,60.5
RAM1_DATA5: HDR1.51 U1.AB7 | length 15.9
  Bottom Layer w0.2: U1.AB7@29.7,47.1 29.7,47.9 29.3,48.3 29.3,51.1 34.9,56.7 HDR1.51@34.9,60.5
RAM1_DATA6: HDR1.47 U1.AB6 | length 15.5
  Bottom Layer w0.2: U1.AB6@28.7,47.1 28.7,47.7 28.5,47.9 28.5,51.431 33.3,56.231 HDR1.47@33.3,60.5
RAM1_DATA7: HDR1.43 U1.AB5 | length 15.1
  Bottom Layer w0.2: U1.AB5@27.7,47.1 27.7,51.763 31.7,55.763 HDR1.43@31.7,60.5
RAM1_OE: HDR1.39 U1.W10 | length 17.5
  MidLayer1 w0.127: 31.7,45.1 31.7,46.1
  MidLayer1 w0.2: v1(30.1,57.7) 31.7,56.1 31.7,46.1 ; 31.7,45.1 v1(32.2,44.6)
  Bottom Layer w0.2: v1(30.1,57.7) HDR1.39@30.1,60.5 ; v1(32.2,44.6) U1.W10@32.7,44.1
RAM1_WE: HDR1.61 U1.AA9 | length 17.4
  Bottom Layer w0.2: U1.AA9@31.7,46.1 32.2,46.6 32.2,51 38.9,57.7 HDR1.61@38.9,60.5
RAM_ADDR0: HDR1.21 U1.W6 | length 19.3
  MidLayer1 w0.2: v1(22.9,58.9) 22.9,56.6 22.3,56 22.3,50.8 23.554,49.546 23.554,49.246 v1(28.2,44.6)
  Bottom Layer w0.2: v1(22.9,58.9) HDR1.21@22.9,60.5 ; v1(28.2,44.6) U1.W6@28.7,44.1
RAM_ADDR1: HDR1.25 U1.W7 | length 19
  MidLayer1 w0.127: 28.7,45.1 28.7,46.1
  MidLayer1 w0.2: v1(24.5,58.9) 24.5,56.5 24,56 24,53.3 28.7,48.6 28.7,46.1 ; 28.7,45.1 v1(29.2,44.6)
  Bottom Layer w0.2: v1(24.5,58.9) HDR1.25@24.5,60.5 ; v1(29.2,44.6) U1.W7@29.7,44.1
RAM_ADDR2: HDR1.29 U1.W9 | length 19.1
  MidLayer1 w0.2: v1(26.1,58.9) 26.1,57.6 25.7,57.2 25.7,52.9 29.822,48.778 29.822,45.978 v1(31.2,44.6)
  Bottom Layer w0.2: v1(26.1,58.9) HDR1.29@26.1,60.5 ; v1(31.2,44.6) U1.W9@31.7,44.1
RAM_ADDR3: HDR1.33 U1.AB4 | length 14.9
  Bottom Layer w0.2: U1.AB4@26.7,47.1 26.7,51.894 29,54.194 ; HDR1.33@27.7,60.5 27.7,59 29,57.7 29,54.2 28.997,54.197
RAM_ADDR4: HDR1.65 U1.AA13 | length 16.4
  Bottom Layer w0.2: U1.AA13@35.7,46.1 36.2,46.6 36.2,47.5 36.3,47.6 36.3,50.4 40.5,54.6 HDR1.65@40.5,60.5
RAM_ADDR5: HDR1.69 U1.AA14 | length 16.6
  Bottom Layer w0.2: U1.AA14@36.7,46.1 37.2,46.6 37.2,49.8 42.1,54.7 HDR1.69@42.1,60.5
RAM_ADDR6: HDR1.73 U1.AA15 | length 16.9
  Bottom Layer w0.2: U1.AA15@37.7,46.1 38.2,46.6 38.2,48.3 43.7,53.8 HDR1.73@43.7,60.5
RAM_ADDR7: HDR1.77 U1.AA16 | length 17.5
  Bottom Layer w0.2: U1.AA16@38.7,46.1 39.2,46.6 39.2,48.1 45.7,54.6 45.7,58.7 45.3,59.1 HDR1.77@45.3,60.5
RAM_ADDR8: HDR1.75 U1.AB16 | length 15.8
  Bottom Layer w0.2: U1.AB16@38.7,47.1 38.7,48.2 44.1,53.6 44.1,58.7 44.5,59.1 HDR1.75@44.5,60.5
RAM_ADDR9: HDR1.71 U1.AB15 | length 15.6
  Bottom Layer w0.2: U1.AB15@37.7,47.1 37.7,48.5 42.9,53.7 HDR1.71@42.9,60.5
RAM_ADDR10: HDR1.67 U1.AB14 | length 15.3
  Bottom Layer w0.2: U1.AB14@36.7,47.1 36.7,50.1 41.3,54.7 HDR1.67@41.3,60.5
RAM_ADDR11: HDR1.63 U1.AB10 | length 16.4
  Bottom Layer w0.2: U1.AB10@32.7,47.1 32.7,49.9 32.6,50 32.6,50.8 39.7,57.9 HDR1.63@39.7,60.5
RAM_ADDR12: HDR1.59 U1.AB9 | length 16.1
  Bottom Layer w0.2: U1.AB9@31.7,47.1 31.7,48.7 31.8,48.8 31.8,51.2 38.1,57.5 HDR1.59@38.1,60.5
RAM_ADDR13: HDR1.35 U1.AA4 | length 15.9
  Bottom Layer w0.2: U1.AA4@26.7,46.1 27.2,46.6 27.2,51.828 29.4,54.028 29.4,57.9 28.5,58.8 HDR1.35@28.5,60.5
RAM_ADDR14: HDR1.31 U1.AA3 | length 16.3
  Bottom Layer w0.2: U1.AA3@25.7,46.1 26.2,46.6 26.2,52 28.6,54.4 28.6,57.534 26.9,59.234 HDR1.31@26.9,60.5
RAM_ADDR15: HDR1.27 U1.Y7 | length 17.2
  MidLayer1 w0.2: v1(25.3,58.4) 25.3,52.7 29.2,48.8 v1(29.2,45.6)
  Bottom Layer w0.2: v1(25.3,58.4) 25.3,58.5 HDR1.27@25.3,60.5 ; v1(29.2,45.6) U1.Y7@29.7,45.1
RAM_ADDR16: HDR1.23 U1.Y6 | length 18.3
  MidLayer1 w0.2: v1(23.7,58.4) 23.7,56.8 22.7,55.8 22.7,51.1 v1(28.2,45.6)
  Bottom Layer w0.2: v1(23.7,58.4) HDR1.23@23.7,60.5 ; v1(28.2,45.6) U1.Y6@28.7,45.1
RAM_CS: HDR1.37 U1.Y8 | length 16.4
  MidLayer1 w0.2: v1(29.3,58.9) 29.3,49.866 31.2,47.966 v1(31.2,45.6)
  Bottom Layer w0.2: v1(29.3,58.9) HDR1.37@29.3,60.5 ; U1.Y8@30.7,45.1 v1(31.2,45.6)
RED0: HDR1.6 U1.K3 | length 49.8
  MidLayer1 w0.2: v1(16.5,69.6) 16.5,65.294 11.7,60.494 11.7,55.6 15.3,52 15.3,37.297 17.997,34.6 v1(25.2,34.6)
  Bottom Layer w0.2: HDR1.6@16.5,67.3 v1(16.5,69.6) ; v1(25.2,34.6) U1.K3@25.7,35.1
RED1: HDR1.8 U1.L4 | length 49.1
  MidLayer1 w0.127: 24.7,35.1 25.7,35.1
  MidLayer1 w0.2: v1(17.3,68.9) 17.3,65.528 12.1,60.328 12.1,55.8 15.7,52.2 15.7,41.4 15.7,37.463 18.063,35.1 24.7,35.1 ; 25.7,35.1 v1(26.2,35.6)
  Bottom Layer w0.2: HDR1.8@17.3,67.3 v1(17.3,68.9) ; v1(26.2,35.6) U1.L4@26.7,36.1
REF_CLK: HDR2.4 TP8.1 U1.B11 | length 29.7
  Top Layer w0.2: TP8.1@14,18.5 18.5,18.5 20.1,20.1 22.2,20.1 23.1,21 23.4,21 23.8,21.4 24.4,21.4 25.4,22.4 26.9,22.4 28,23.5 31.9,23.5 32.9,24.5 v1(33.8,24.5)
  MidLayer1 w0.2: v1(33.2,27.6) 33.2,25.1 v1(33.8,24.5)
  Bottom Layer w0.2: TP8.1@14,18.5 15.2,18.5 15.7,18 HDR2.4@15.7,16.5 ; v1(33.2,27.6) U1.B11@33.7,27.1
SCL: HDR2.5 U1.P19 U2.14 | length 110.6
  Top Layer w0.2: U2.14@3.047,24.5 U2.14@3.047,24.6 3.047,26.247 v1(3.4,26.6)
  Top Layer w0.3: v1(12.8,5.8) 13.4,6.4 16,6.4 16.5,6.9 v1(16.5,7.7)
  MidLayer2 w0.127: 42.7,39.1 43.7,39.1
  MidLayer2 w0.2: v1(42.2,38.6) 42.7,39.1 ; 43.7,39.1 45.6,39.1 46.9,37.8 46.9,36.3 49.4,33.8 49.4,25.6 48.4,24.6 48.4,21 48.303,20.903 ; v1(46.9,6.6) 46.9,7.3 47.5,7.9 47.5,20.1 47.7,20.3 48.3,20.906
  Bottom Layer w0.2: v1(3.4,26.6) 1.9,25.1 1.9,18.1 2.9,17.1 4.2,15.8 4.2,10.2 8.6,5.8 v1(12.8,5.8) ; HDR2.5@16.5,9.7 v1(16.5,7.7) 20.9,3.3 43.5,3.3 v1(46.9,6.6) ; U1.P19@41.7,39.1 v1(42.2,38.6)
SDA: HDR2.3 U1.R20 U2.12 | length 107.5
  Top Layer w0.2: v1(4.3,22.8) 4.3,24.582 U2.12@4.317,24.6
  Top Layer w0.3: v1(12.1,6.4) 12.8,7.1 v1(15.7,7.1)
  MidLayer2 w0.2: v1(43.2,39.6) 45.7,39.6 47.3,38 47.3,36.5 49.8,34 49.8,21.8 48.3,20.3 48.3,11.5 47.9,11.1 47.9,7.9 48.5,7.3 v1(48.6,6.8)
  Bottom Layer w0.2: v1(4.3,22.8) 2.8,22.8 2.3,22.3 2.3,18.3 4.6,16 4.6,10.366 8.566,6.4 v1(12.1,6.4) ; HDR2.3@15.7,9.7 v1(15.7,7.1) 18.439,4.361 19.239,4.361 20.7,2.9 44.6,2.9 v1(48.6,6.8) ; U1.R20@42.7,40.1 v1(43.2,39.6)
SP0: HDR2.79 U1.D18 | length 27.1
  MidLayer1 w0.127: 40.7,27.1 40.7,28.1
  MidLayer1 w0.2: v1(40.2,28.6) 40.7,28.1 ; 40.7,27.1 46.1,21.7 v1(46.1,7.2)
  Bottom Layer w0.2: v1(40.2,28.6) U1.D18@40.7,29.1 ; v1(46.1,7.2) 46.1,7.3 HDR2.79@46.1,9.7
SP1: HDR2.81 U1.C18 | length 24
  MidLayer1 w0.2: v1(41.2,27.6) 46.9,21.9 v1(46.9,8.2)
  Bottom Layer w0.2: U1.C18@40.7,28.1 v1(41.2,27.6) ; v1(46.9,8.2) HDR2.81@46.9,9.7
SP2: HDR2.83 U1.F18 | length 29.3
  MidLayer1 w0.2: v1(41.2,30.6) 41.2,29.6 44.4,26.4 44.4,25.4 47.7,22.1 v1(47.7,7.2)
  Bottom Layer w0.2: U1.F18@40.7,31.1 v1(41.2,30.6) ; v1(47.7,7.2) 47.7,7.3 HDR2.83@47.7,9.7
SP3: HDR2.85 U1.E19 | length 27.9
  MidLayer1 w0.127: 42.7,30.1 43.7,30.1
  MidLayer1 w0.2: v1(42.2,29.6) 42.7,30.1 ; 43.7,30.1 43.8,30.1 46.7,27.2 46.7,23.9 48.5,22.1 v1(48.5,8.2)
  Bottom Layer w0.2: U1.E19@41.7,30.1 v1(42.2,29.6) ; v1(48.5,8.2) HDR2.85@48.5,9.7
SP4: HDR2.87 U1.E20 | length 29.5
  MidLayer1 w0.2: v1(43.2,30.6) 44,30.6 47.2,27.4 47.2,24.3 49.4,22.1 v1(49.4,7.3)
  Bottom Layer w0.2: U1.E20@42.7,30.1 v1(43.2,30.6) ; HDR2.87@49.3,9.7 49.3,7.3 v1(49.4,7.3)
SP5: HDR2.89 U1.F19 | length 30.2
  MidLayer1 w0.127: 42.7,31.1 43.7,31.1
  MidLayer1 w0.2: v1(42.2,30.6) 42.7,31.1 ; 43.7,31.1 44.4,31.1 49.9,25.6 49.9,18.5 50.3,18.1 v1(50.3,8.2)
  Bottom Layer w0.2: U1.F19@41.7,31.1 v1(42.2,30.6) ; HDR2.89@50.1,9.7 50.1,8.2 v1(50.3,8.2)
SP6: HDR2.91 U1.F20 | length 31.7
  MidLayer1 w0.2: v1(43.2,31.6) 45,31.6 50.3,26.3 50.3,18.9 50.9,18.3 v1(50.9,7.4)
  Bottom Layer w0.2: U1.F20@42.7,31.1 v1(43.2,31.6) ; HDR2.91@50.9,9.7 v1(50.9,7.4) ; v1(50.9,7.4) 50.9,7.3 v1(50.9,7.4)
SP7: HDR2.92 U1.B19 | length 14.6
  Bottom Layer w0.2: U1.B19@41.7,27.1 42.2,26.6 42.2,25.7 42.5,25.4 42.9,25.4 50.9,17.4 HDR2.92@50.9,16.5
SP8: HDR2.90 U1.A19 | length 13.4
  Bottom Layer w0.2: U1.A19@41.7,26.1 41.7,25.4 42.1,25 42.6,25 50.1,17.5 HDR2.90@50.1,16.5
SP9: HDR2.88 U1.B18 | length 14.5
  Bottom Layer w0.2: U1.B18@40.7,27.1 41.2,26.6 41.2,25.3 41.9,24.6 42.4,24.6 49.3,17.7 HDR2.88@49.3,16.5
